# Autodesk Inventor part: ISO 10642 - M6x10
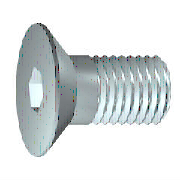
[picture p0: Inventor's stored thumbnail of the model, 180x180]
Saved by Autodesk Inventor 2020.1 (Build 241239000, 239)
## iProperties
Created: 2019-01
Part Number: ISO 10642 - M6x10
Material: Stahl, weich
Description: Senkschrauben mit Innensechskant
Document SubType Name: Modeling
Standard: ISO 10642
Designer: lutzd
Standards Organization: ISO
Language: de-DE
Size Designation: M6x10
Categories: <MemberInstance><Categories><Category DisplayName="Verbindungselemente" InternalName="e4da775c-781d-43d5-af7c-5136215cf5a6" Mnemonic="FSTN"><Category DisplayNam
Mass: 3.018 g
Surface Area: 4.27493 cm^2
Volume: 0.384458 cm^3
Density: 7.85 g/cm^3
Appearance: Halbpoliert
IsCustomPart: 0
Author: lutzd
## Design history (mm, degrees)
node "WorkPoint1"
sketch "Skizze2"
  geometry: L1 (-3, -10)-(0, -10); L2 (-3, -3.3)-(-3, -10); L3 (-6, -0.3)-(-3, -3.3); L4 (-6, 0)-(-6, -0.3); L5 (0, 0)-(-6, 0); L6 (0, -10)-(0, 0); L7 (0, -10)-(0, 0); L8 (0, -12)-(0, 2) reference; L9 (1.2, 0)-(-7.2, 0) reference
  constraints: 14 end point, 3 vertical, 2 horizontal
  dimensions: "d3" = 6 distance of L5.start L4.start (= 0.5 x dk); "d5" = 3 distance of L1.start L1.end (= 0.5 x NND); "d7" = 10 distance of L1.end L5.start (= NLG); "ParC" = 0.3 distance of L4.start L3.start; "d22" = 0 distance between parallel lines of L8 L6; "d23" = 0 distance between parallel lines of L9 L5; "d43" = 45 deg angle of L6 L3 (= 0.5 x ang)
revolve "Drehung1" stored, may be unused: angle "d8" = 360 deg
node "MSC_A1"
node "MSC_PF1"
node "MSC_PT1"
body "Solid1"
node "Skizze1"
sketch "Skizze3"
  geometry: L1 (-2, 1.155)-(-2, -1.155); L2 (0, 2.309)-(-2, 1.155); L3 (2, 1.155)-(0, 2.309); L4 (2, -1.155)-(2, 1.155); L5 (0, -2.309)-(2, -1.155); L6 (-2, -1.155)-(0, -2.309); C1 r 2 at (0, 0); C2 r 3 at (0, 0) reference
  constraints: 12 end point, 6 tangent, 2 parallel, 2 vertical, 1 centre point, 1 concentric
  dimensions: "d11" = 4 diameter of C1 (= ParS); "d13" = 120 deg angle of L1 L2; "d15" = 120 deg angle of L6 L1
extrude "Extrusion1" cut sketch "Skizze3" distance "d16" = 2.5 (= ParT); taper "d17" = 0 deg
fillet "Rundung1" dims "d18" = 0.3 (= r)
chamfer "Fase1" distance "d19" = 0.5 (= 0.5 x PTC); stored, may be unused: angle "d20" = 45 deg, second distance "d39" = 0.5 (= 0.5 x PTC)
feature "Gewinde1" dims "d35" = 0, "b" = 4.7
other parameters: "NND" = 6 [user parameter; used in 2 equation terms], "PTC" = 1 [user parameter; used in 2 equation terms], "dk" = 12 [user parameter; used in 1 equation term], "ParK" = 3.3 [user parameter], "ParS" = 4 [user parameter; used in 1 equation term], "ParT" = 2.5 [user parameter; used in 1 equation term], "r" = 0.3 [user parameter; used in 1 equation term], "NLG" = 10 [user parameter; used in 1 equation term], "d0" = 45 deg (derived), "d2" = 3 (derived), "d4" = 1.5 (derived), "d6" = 8 (derived), "d9" = 0, "d10" = 2 (derived), "d12" = 120 deg (derived), "d14" = 120 deg (derived), "d37" = 0, "d38" = 0, "d40" = 0, "d41" = 0, "d42" = 0, "ang" = 90 deg [user parameter; used in 1 equation term], "THREADDIA" = 6 (= NND) [user parameter]
